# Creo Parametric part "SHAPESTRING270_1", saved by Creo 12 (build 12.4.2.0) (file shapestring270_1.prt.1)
Units: Custom; MM, KILOGRAM, SECS

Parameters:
  PTC_WM_ITERATION = "0"
  PTC_WM_VERSION = "-.0"
  PTC_WM_LIFECYCLE_STATE = "In Work"
  PTC_WM_LIFECYCLE = "MO_CADDocument"
  PTC_WM_CREATED_BY = "Maximilian Roepper (Z0017RMS: MO)"
  PTC_WM_CREATED_ON = "18-Sep-26 11:36:42 AM"
  PTC_WM_MODIFIED_BY = "Maximilian Roepper (Z0017RMS: MO)"
  PTC_WM_MODIFIED_ON = "18-Sep-26 11:36:46 AM"
  PDMLINKNUMBER = "PDM000071455240"
  PTC_WM_NAME = "shapestring270_1.prt"
  PTC_WM_NUMBER = "PDM000071455240"

Other parameters: WEIGHT, WEIGHT_FACTOR, WEIGHT_ADD, _MASS_TEMP, _DIFF_TEMP, MC_ERRORS, SUPPLIER

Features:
  1. coordinate system
  2. datum plane "PRT_YZ"
  3. datum plane "PRT_XY"
  4. datum plane "PRT_XZ"
  5. coordinate system
  6. datum axis
  7. datum axis
  8. datum axis
  9. coordinate system
  10. imported feature
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
Other named items: PRT, SIEMENS_MO, DRW_VIEW_ORG, PRT_X, PRT_Y, PRT_Z, CS0, ROUGH_GROB

Layers: 00_STD_CSYS-KSYS, 01_STD_PLANES-EBENEN, 02_STD_AXES-ACHSEN, 03_STD_CSYS-KSYS, 24_IMPORT_FEAT-IMPORT_KE, WHITE

Surfaces: 1 plane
